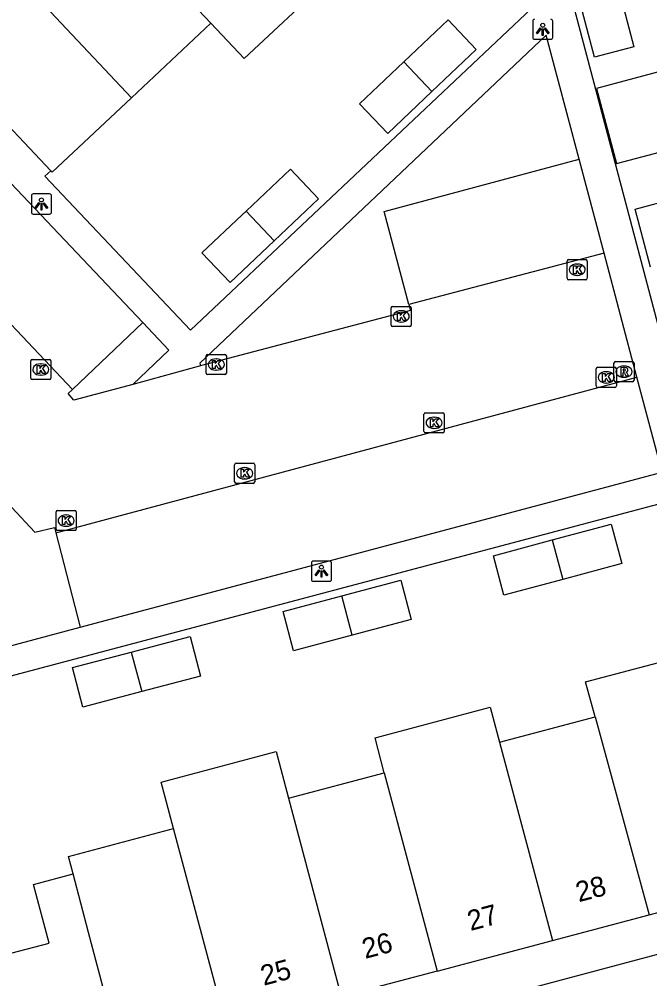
# Model space of a CAD drawing. Extents: x 162542 to 163144, y 380786 to 381511.
# Drawn here: x 162698.04 to 162729.3, y 381201.72 to 381249.34 of the extents above; entities that cross this region are included whole.
import ezdxf

# ---------------------------------------------------------------- set-up
doc = ezdxf.new("R2010")
doc.units = 0
for name, color, linetype in [('IMGEO_Kolk', 7, 'Continuous'), ('IMGEO_Lichtpunt', 7, 'Continuous'), ('IMGEO_Pand', 7, 'Continuous'), ('IMGEO_Pand_nummerreeks', 7, 'Continuous'), ('IMGEO_Parkeervlak_open', 7, 'Continuous'), ('IMGEO_Rijbaan_lokaal_open', 7, 'Continuous'), ('IMGEO_Rioolput', 7, 'Continuous'), ('IMGEO_Voetpad_open', 7, 'Continuous')]:
    doc.layers.add(name, color=color, linetype=linetype)

msp = doc.modelspace()

# ---------------------------------------------------------------- linework, layer by layer
at = {"layer": 'IMGEO_Kolk'}
for p, q in [((162725.2, 381236.483), (162725.2, 381237.335)), ((162725.275, 381237.409), (162726.127, 381237.409)), ((162725.688, 381237.189), (162725.713, 381237.189)), ((162726.201, 381237.335), (162726.201, 381236.483)), ((162725.711, 381236.629), (162725.686, 381236.629)), ((162726.127, 381236.409), (162725.275, 381236.409)), ((162716.476, 381234.166), (162716.476, 381235.018)), ((162716.551, 381235.092), (162717.403, 381235.092)), ((162716.964, 381234.872), (162716.989, 381234.872)), ((162717.477, 381235.018), (162717.477, 381234.166)), ((162716.987, 381234.312), (162716.962, 381234.312)), ((162717.403, 381234.092), (162716.551, 381234.092)), ((162698.607, 381231.533), (162698.607, 381232.385)), ((162698.682, 381232.459), (162699.534, 381232.459)), ((162699.608, 381232.385), (162699.608, 381231.533)), ((162707.307, 381231.779), (162707.307, 381232.631)), ((162707.382, 381232.705), (162708.234, 381232.705)), ((162707.795, 381232.485), (162707.82, 381232.485)), ((162708.308, 381232.631), (162708.308, 381231.779)), ((162699.095, 381232.239), (162699.12, 381232.239)), ((162707.818, 381231.925), (162707.793, 381231.925)), ((162726.643, 381231.14), (162726.643, 381231.992)), ((162726.718, 381232.066), (162727.57, 381232.066)), ((162727.131, 381231.846), (162727.156, 381231.846)), ((162727.644, 381231.992), (162727.644, 381231.14)), ((162699.534, 381231.459), (162698.682, 381231.459)), ((162699.118, 381231.679), (162699.093, 381231.679)), ((162708.234, 381231.705), (162707.382, 381231.705)), ((162727.57, 381231.066), (162726.718, 381231.066)), ((162727.154, 381231.286), (162727.129, 381231.286)), ((162718.106, 381228.888), (162718.106, 381229.74)), ((162718.181, 381229.814), (162719.033, 381229.814)), ((162718.594, 381229.594), (162718.619, 381229.594)), ((162719.107, 381229.74), (162719.107, 381228.888)), ((162718.617, 381229.034), (162718.592, 381229.034)), ((162719.033, 381228.814), (162718.181, 381228.814)), ((162708.714, 381226.382), (162708.714, 381227.234)), ((162708.789, 381227.308), (162709.641, 381227.308)), ((162709.202, 381227.088), (162709.227, 381227.088)), ((162709.715, 381227.234), (162709.715, 381226.382)), ((162709.641, 381226.308), (162708.789, 381226.308)), ((162709.225, 381226.528), (162709.2, 381226.528)), ((162699.861, 381224.036), (162699.861, 381224.888)), ((162699.936, 381224.962), (162700.788, 381224.962)), ((162700.349, 381224.742), (162700.374, 381224.742)), ((162700.862, 381224.888), (162700.862, 381224.036)), ((162700.788, 381223.962), (162699.936, 381223.962)), ((162700.372, 381224.182), (162700.347, 381224.182))]:
    msp.add_line(p, q, dxfattribs=at)
for points in [[(162725.2, 381236.483), (162725.2, 381237.335)], [(162725.275, 381237.409), (162726.127, 381237.409)], [(162725.521, 381237.109), (162725.644, 381237.109), (162725.644, 381236.958), (162725.774, 381237.109), (162725.938, 381237.109), (162725.792, 381236.958), (162725.945, 381236.709), (162725.793, 381236.709), (162725.708, 381236.873), (162725.644, 381236.806), (162725.644, 381236.709), (162725.521, 381236.709), (162725.521, 381237.109)], [(162726.201, 381237.335), (162726.201, 381236.483)], [(162726.127, 381236.409), (162725.275, 381236.409)], [(162716.476, 381234.166), (162716.476, 381235.018)], [(162716.551, 381235.092), (162717.403, 381235.092)], [(162716.797, 381234.792), (162716.92, 381234.792), (162716.92, 381234.641), (162717.05, 381234.792), (162717.214, 381234.792), (162717.068, 381234.641), (162717.221, 381234.392), (162717.069, 381234.392), (162716.984, 381234.556), (162716.92, 381234.489), (162716.92, 381234.392), (162716.797, 381234.392), (162716.797, 381234.792)], [(162717.477, 381235.018), (162717.477, 381234.166)], [(162717.403, 381234.092), (162716.551, 381234.092)], [(162698.607, 381231.533), (162698.607, 381232.385)], [(162698.682, 381232.459), (162699.534, 381232.459)], [(162699.608, 381232.385), (162699.608, 381231.533)], [(162707.307, 381231.779), (162707.307, 381232.631)], [(162707.382, 381232.705), (162708.234, 381232.705)], [(162707.628, 381232.405), (162707.751, 381232.405), (162707.751, 381232.254), (162707.881, 381232.405), (162708.045, 381232.405), (162707.899, 381232.254), (162708.052, 381232.005), (162707.9, 381232.005), (162707.815, 381232.169), (162707.751, 381232.102), (162707.751, 381232.005), (162707.628, 381232.005), (162707.628, 381232.405)], [(162708.308, 381232.631), (162708.308, 381231.779)], [(162698.928, 381232.159), (162699.051, 381232.159), (162699.051, 381232.008), (162699.181, 381232.159), (162699.345, 381232.159), (162699.199, 381232.008), (162699.352, 381231.759), (162699.2, 381231.759), (162699.115, 381231.923), (162699.051, 381231.856), (162699.051, 381231.759), (162698.928, 381231.759), (162698.928, 381232.159)], [(162726.643, 381231.14), (162726.643, 381231.992)], [(162726.718, 381232.066), (162727.57, 381232.066)], [(162727.644, 381231.992), (162727.644, 381231.14)], [(162699.534, 381231.459), (162698.682, 381231.459)], [(162708.234, 381231.705), (162707.382, 381231.705)], [(162726.964, 381231.766), (162727.087, 381231.766), (162727.087, 381231.615), (162727.217, 381231.766), (162727.381, 381231.766), (162727.235, 381231.615), (162727.388, 381231.366), (162727.236, 381231.366), (162727.151, 381231.53), (162727.087, 381231.463), (162727.087, 381231.366), (162726.964, 381231.366), (162726.964, 381231.766)], [(162727.57, 381231.066), (162726.718, 381231.066)], [(162718.106, 381228.888), (162718.106, 381229.74)], [(162718.181, 381229.814), (162719.033, 381229.814)], [(162718.427, 381229.514), (162718.55, 381229.514), (162718.55, 381229.363), (162718.68, 381229.514), (162718.844, 381229.514), (162718.698, 381229.363), (162718.851, 381229.114), (162718.699, 381229.114), (162718.614, 381229.278), (162718.55, 381229.211), (162718.55, 381229.114), (162718.427, 381229.114), (162718.427, 381229.514)], [(162719.107, 381229.74), (162719.107, 381228.888)], [(162719.033, 381228.814), (162718.181, 381228.814)], [(162708.714, 381226.382), (162708.714, 381227.234)], [(162708.789, 381227.308), (162709.641, 381227.308)], [(162709.715, 381227.234), (162709.715, 381226.382)], [(162709.035, 381227.008), (162709.158, 381227.008), (162709.158, 381226.857), (162709.288, 381227.008), (162709.452, 381227.008), (162709.306, 381226.857), (162709.459, 381226.608), (162709.307, 381226.608), (162709.222, 381226.772), (162709.158, 381226.705), (162709.158, 381226.608), (162709.035, 381226.608), (162709.035, 381227.008)], [(162709.641, 381226.308), (162708.789, 381226.308)], [(162699.861, 381224.036), (162699.861, 381224.888)], [(162699.936, 381224.962), (162700.788, 381224.962)], [(162700.862, 381224.888), (162700.862, 381224.036)], [(162700.182, 381224.662), (162700.305, 381224.662), (162700.305, 381224.511), (162700.435, 381224.662), (162700.599, 381224.662), (162700.453, 381224.511), (162700.606, 381224.262), (162700.454, 381224.262), (162700.369, 381224.426), (162700.305, 381224.359), (162700.305, 381224.262), (162700.182, 381224.262), (162700.182, 381224.662)], [(162700.788, 381223.962), (162699.936, 381223.962)]]:
    msp.add_lwpolyline(points, dxfattribs=at)
for centre, start, end in [((162725.277, 381237.333), 91.552, 178.448), ((162725.277, 381237.333), 91.552, 178.448), ((162726.125, 381237.333), 1.552, 88.448), ((162726.125, 381237.333), 1.552, 88.448), ((162725.277, 381236.485), 181.552, 268.448), ((162725.277, 381236.485), 181.552, 268.448), ((162726.125, 381236.485), 271.552, 358.448), ((162726.125, 381236.485), 271.552, 358.448), ((162716.553, 381235.016), 91.552, 178.448), ((162716.553, 381235.016), 91.552, 178.448), ((162717.401, 381235.016), 1.552, 88.448), ((162717.401, 381235.016), 1.552, 88.448), ((162716.553, 381234.168), 181.552, 268.448), ((162716.553, 381234.168), 181.552, 268.448), ((162717.401, 381234.168), 271.552, 358.448), ((162717.401, 381234.168), 271.552, 358.448), ((162698.684, 381232.383), 91.552, 178.448), ((162698.684, 381232.383), 91.552, 178.448), ((162699.532, 381232.383), 1.552, 88.448), ((162699.532, 381232.383), 1.552, 88.448), ((162707.384, 381232.629), 91.552, 178.448), ((162707.384, 381232.629), 91.552, 178.448), ((162708.232, 381232.629), 1.552, 88.448), ((162708.232, 381232.629), 1.552, 88.448), ((162726.72, 381231.99), 91.552, 178.448), ((162726.72, 381231.99), 91.552, 178.448), ((162727.568, 381231.99), 1.552, 88.448), ((162727.568, 381231.99), 1.552, 88.448), ((162698.684, 381231.535), 181.552, 268.448), ((162698.684, 381231.535), 181.552, 268.448), ((162699.532, 381231.535), 271.552, 358.448), ((162699.532, 381231.535), 271.552, 358.448), ((162707.384, 381231.781), 181.552, 268.448), ((162707.384, 381231.781), 181.552, 268.448), ((162708.232, 381231.781), 271.552, 358.448), ((162708.232, 381231.781), 271.552, 358.448), ((162726.72, 381231.142), 181.552, 268.448), ((162726.72, 381231.142), 181.552, 268.448), ((162727.568, 381231.142), 271.552, 358.448), ((162727.568, 381231.142), 271.552, 358.448), ((162718.183, 381229.738), 91.552, 178.448), ((162718.183, 381229.738), 91.552, 178.448), ((162719.031, 381229.738), 1.552, 88.448), ((162719.031, 381229.738), 1.552, 88.448), ((162718.183, 381228.89), 181.552, 268.448), ((162718.183, 381228.89), 181.552, 268.448), ((162719.031, 381228.89), 271.552, 358.448), ((162719.031, 381228.89), 271.552, 358.448), ((162708.791, 381227.232), 91.552, 178.448), ((162708.791, 381227.232), 91.552, 178.448), ((162709.639, 381227.232), 1.552, 88.448), ((162709.639, 381227.232), 1.552, 88.448), ((162708.791, 381226.384), 181.552, 268.448), ((162708.791, 381226.384), 181.552, 268.448), ((162709.639, 381226.384), 271.552, 358.448), ((162709.639, 381226.384), 271.552, 358.448), ((162699.938, 381224.886), 91.552, 178.448), ((162699.938, 381224.886), 91.552, 178.448), ((162700.786, 381224.886), 1.552, 88.448), ((162700.786, 381224.886), 1.552, 88.448), ((162699.938, 381224.038), 181.552, 268.448), ((162699.938, 381224.038), 181.552, 268.448), ((162700.786, 381224.038), 271.552, 358.448), ((162700.786, 381224.038), 271.552, 358.448)]:
    msp.add_arc(centre, 0.0765, start, end, dxfattribs=at)
for centre, major_axis, ratio, start_param, end_param in [((162725.687, 381236.909), (-0.387, 0.002), 0.722429, 4.712389, 7.853982), ((162725.712, 381236.909), (-0.39, 0.002), 0.717154, 1.570796, 4.712389), ((162716.963, 381234.592), (-0.387, 0.002), 0.722429, 4.712389, 7.853982), ((162716.988, 381234.592), (-0.39, 0.002), 0.717154, 1.570796, 4.712389), ((162707.794, 381232.205), (-0.387, 0.002), 0.722429, 4.712389, 7.853982), ((162707.819, 381232.205), (-0.39, 0.002), 0.717154, 1.570796, 4.712389), ((162699.094, 381231.959), (-0.387, 0.002), 0.722429, 4.712389, 7.853982), ((162699.119, 381231.959), (-0.39, 0.002), 0.717154, 1.570796, 4.712389), ((162727.13, 381231.566), (-0.387, 0.002), 0.722429, 4.712389, 7.853982), ((162727.155, 381231.566), (-0.39, 0.002), 0.717154, 1.570796, 4.712389), ((162718.593, 381229.314), (-0.387, 0.002), 0.722429, 4.712389, 7.853982), ((162718.618, 381229.314), (-0.39, 0.002), 0.717154, 1.570796, 4.712389), ((162709.201, 381226.808), (-0.387, 0.002), 0.722429, 4.712389, 7.853982), ((162709.226, 381226.808), (-0.39, 0.002), 0.717154, 1.570796, 4.712389), ((162700.348, 381224.462), (-0.387, 0.002), 0.722429, 4.712389, 7.853982), ((162700.373, 381224.462), (-0.39, 0.002), 0.717154, 1.570796, 4.712389)]:
    msp.add_ellipse(centre, major_axis=major_axis, ratio=ratio, start_param=start_param, end_param=end_param, dxfattribs=at)
at = {"layer": 'IMGEO_Lichtpunt'}
for p, q in [((162723.495, 381249.246), (162723.495, 381248.439)), ((162723.495, 381249.246), (162723.495, 381248.439)), ((162724.491, 381248.439), (162724.491, 381249.246)), ((162724.491, 381248.439), (162724.491, 381249.246)), ((162723.589, 381248.345), (162724.397, 381248.345)), ((162723.589, 381248.345), (162724.397, 381248.345)), ((162698.641, 381240.573), (162698.641, 381239.766)), ((162698.641, 381240.573), (162698.641, 381239.766)), ((162699.543, 381240.668), (162698.735, 381240.668)), ((162699.543, 381240.668), (162698.735, 381240.668)), ((162699.637, 381239.766), (162699.637, 381240.573)), ((162699.637, 381239.766), (162699.637, 381240.573)), ((162698.735, 381239.672), (162699.543, 381239.672)), ((162698.735, 381239.672), (162699.543, 381239.672)), ((162712.524, 381222.354), (162712.524, 381221.547)), ((162712.524, 381222.354), (162712.524, 381221.547)), ((162713.426, 381222.449), (162712.618, 381222.449)), ((162713.426, 381222.449), (162712.618, 381222.449)), ((162713.52, 381221.547), (162713.52, 381222.354)), ((162713.52, 381221.547), (162713.52, 381222.354)), ((162712.618, 381221.453), (162713.426, 381221.453)), ((162712.618, 381221.453), (162713.426, 381221.453))]:
    msp.add_line(p, q, dxfattribs=at)
for points in [[(162723.869, 381248.91), (162723.908, 381248.882), (162723.72, 381248.62), (162723.682, 381248.647), (162723.869, 381248.91)], [(162723.971, 381248.862), (162724.018, 381248.862), (162724.018, 381248.54), (162723.971, 381248.54), (162723.971, 381248.862)], [(162724.081, 381248.882), (162724.119, 381248.909), (162724.306, 381248.647), (162724.267, 381248.619), (162724.081, 381248.882)], [(162699.015, 381240.237), (162699.054, 381240.209), (162698.866, 381239.947), (162698.828, 381239.974), (162699.015, 381240.237)], [(162699.117, 381240.189), (162699.164, 381240.189), (162699.164, 381239.867), (162699.117, 381239.867), (162699.117, 381240.189)], [(162699.227, 381240.209), (162699.265, 381240.236), (162699.452, 381239.974), (162699.413, 381239.946), (162699.227, 381240.209)], [(162712.898, 381222.018), (162712.937, 381221.99), (162712.749, 381221.728), (162712.711, 381221.755), (162712.898, 381222.018)], [(162713, 381221.97), (162713.047, 381221.97), (162713.047, 381221.648), (162713, 381221.648), (162713, 381221.97)], [(162713.11, 381221.99), (162713.148, 381222.017), (162713.335, 381221.755), (162713.296, 381221.727), (162713.11, 381221.99)]]:
    msp.add_lwpolyline(points, dxfattribs=at)
for centre in [(162723.994, 381249.044), (162699.14, 381240.371), (162713.023, 381222.152)]:
    msp.add_circle(centre, 0.0994, dxfattribs=at)
for centre, start, end in [((162723.589, 381249.246), 90, 180), ((162723.589, 381249.246), 90, 180), ((162724.397, 381249.246), 0, 90), ((162724.397, 381249.246), 0, 90), ((162723.589, 381248.439), 180, 270), ((162723.589, 381248.439), 180, 270), ((162724.397, 381248.439), 270, 0), ((162724.397, 381248.439), 270, 360), ((162698.735, 381240.573), 90, 180), ((162698.735, 381240.573), 90, 180), ((162699.543, 381240.573), 0, 90), ((162699.543, 381240.573), 0, 90), ((162698.735, 381239.766), 180, 270), ((162698.735, 381239.766), 180, 270), ((162699.543, 381239.766), 270, 0), ((162699.543, 381239.766), 270, 360), ((162712.618, 381222.354), 90, 180), ((162712.618, 381222.354), 90, 180), ((162713.426, 381222.354), 0, 90), ((162713.426, 381222.354), 0, 90), ((162712.618, 381221.547), 180, 270), ((162712.618, 381221.547), 180, 270), ((162713.426, 381221.547), 270, 0), ((162713.426, 381221.547), 270, 360)]:
    msp.add_arc(centre, 0.0946, start, end, dxfattribs=at)
at = {"layer": 'IMGEO_Pand'}
for points in [[(162707.53, 381249.144), (162700.536, 381256.552)], [(162696.614, 381252.86), (162703.604, 381245.444)], [(162707.53, 381249.144), (162709.189, 381247.387), (162713.298, 381251.249)], [(162728.518, 381247.977), (162726.564, 381247.458), (162725.794, 381250.355), (162727.745, 381250.883), (162728.518, 381247.977)], [(162692.684, 381249.159), (162699.606, 381241.818)], [(162703.604, 381245.444), (162707.53, 381249.144)], [(162718.499, 381245.754), (162720.69, 381247.831), (162719.3, 381249.303), (162717.106, 381247.224)], [(162717.106, 381247.224), (162714.915, 381245.147), (162716.308, 381243.677), (162718.499, 381245.754)], [(162718.499, 381245.754), (162717.106, 381247.224)], [(162730.367, 381246.893), (162726.662, 381245.909), (162727.653, 381242.178), (162731.357, 381243.162), (162730.367, 381246.893)], [(162699.606, 381241.818), (162699.677, 381241.743), (162703.604, 381245.444)], [(162710.683, 381238.348), (162712.876, 381240.422), (162711.482, 381241.895), (162709.289, 381239.822)], [(162729.334, 381237.037), (162728.568, 381239.917), (162730.536, 381240.438), (162731.294, 381237.569)], [(162709.289, 381239.822), (162709.084, 381239.628), (162707.088, 381237.741), (162708.49, 381236.274), (162710.683, 381238.348)], [(162710.683, 381238.348), (162709.289, 381239.822)], [(162724.468, 381223.499), (162727.387, 381224.28), (162727.911, 381222.324), (162724.992, 381221.543)], [(162724.992, 381221.543), (162722.072, 381220.761), (162721.556, 381222.72), (162724.468, 381223.499)], [(162724.468, 381223.499), (162724.992, 381221.543)], [(162714.034, 381220.723), (162716.95, 381221.503), (162717.469, 381219.561), (162714.552, 381218.783)], [(162714.552, 381218.783), (162711.635, 381218.004), (162711.121, 381219.944), (162714.034, 381220.723)], [(162714.552, 381218.783), (162714.034, 381220.723)], [(162703.595, 381217.937), (162706.51, 381218.705), (162707.032, 381216.744), (162704.112, 381215.976)], [(162704.112, 381215.976), (162701.191, 381215.207), (162700.675, 381217.167), (162703.595, 381217.937)], [(162703.595, 381217.937), (162704.112, 381215.976)], [(162726.586, 381214.725), (162726.113, 381216.459), (162731.811, 381217.971), (162731.839, 381217.865)], [(162716.137, 381211.949), (162715.678, 381213.677), (162721.392, 381215.196), (162721.852, 381213.468)], [(162721.852, 381213.468), (162726.586, 381214.725)], [(162726.586, 381214.725), (162729.268, 381204.894)], [(162721.852, 381213.468), (162724.473, 381203.621)], [(162705.693, 381209.175), (162705.078, 381211.488), (162710.779, 381213.004), (162711.391, 381210.689)], [(162711.391, 381210.689), (162716.137, 381211.949)], [(162716.137, 381211.949), (162718.757, 381202.103)], [(162711.391, 381210.689), (162713.994, 381200.841)], [(162700.704, 381206.928), (162700.475, 381207.789), (162705.693, 381209.175)], [(162708.31, 381199.334), (162705.693, 381209.175)], [(162693.566, 381201.906), (162693.946, 381202.007), (162697.691, 381203.007), (162699.525, 381203.496), (162698.751, 381206.41), (162700.704, 381206.928)], [(162703.116, 381197.844), (162701.477, 381204.017), (162700.704, 381206.928)], [(162729.268, 381204.894), (162734.886, 381206.386)], [(162724.473, 381203.621), (162729.268, 381204.894)], [(162718.757, 381202.103), (162724.473, 381203.621)], [(162718.757, 381202.103), (162713.994, 381200.841)]]:
    msp.add_lwpolyline(points, dxfattribs=at)
at = {"layer": 'IMGEO_Parkeervlak_open'}
for points in [[(162717.359, 381235.188), (162716.135, 381239.802), (162725.799, 381242.395)], [(162700.677, 381230.974), (162704.173, 381234.294)], [(162699.849, 381223.847), (162701.06, 381219.172)]]:
    msp.add_lwpolyline(points, dxfattribs=at)
at = {"layer": 'IMGEO_Rijbaan_lokaal_open'}
for points in [[(162700.677, 381230.974), (162688.475, 381243.889), (162691.953, 381247.17)], [(162727.036, 381237.729), (162717.359, 381235.188)], [(162728.656, 381231.579), (162727.036, 381237.729)], [(162717.359, 381235.188), (162717.44, 381234.879), (162707.144, 381232.175), (162707.019, 381232.142)], [(162707.019, 381232.142), (162703.666, 381231.209)], [(162699.849, 381223.847), (162728.656, 381231.579)], [(162703.666, 381231.209), (162700.747, 381230.44), (162700.456, 381230.763), (162700.677, 381230.974)], [(162697.438, 381224.879), (162697.666, 381225.113), (162698.805, 381223.893), (162699.779, 381224.12), (162699.849, 381223.847)]]:
    msp.add_lwpolyline(points, dxfattribs=at)
at = {"layer": 'IMGEO_Rioolput'}
for p, q in [((162727.597, 381232.35), (162728.449, 381232.35)), ((162727.522, 381231.424), (162727.522, 381232.276)), ((162728.01, 381232.13), (162728.035, 381232.13)), ((162728.523, 381232.276), (162728.523, 381231.424)), ((162728.033, 381231.57), (162728.008, 381231.57)), ((162728.449, 381231.35), (162727.597, 381231.35))]:
    msp.add_line(p, q, dxfattribs=at)
for points in [[(162727.597, 381232.35), (162728.449, 381232.35)], [(162727.522, 381231.424), (162727.522, 381232.276)], [(162728.111, 381232.048), (162727.859, 381232.05), (162727.859, 381231.65)], [(162728.037, 381231.969), (162727.983, 381231.969), (162727.983, 381231.888)], [(162727.983, 381231.888), (162728.035, 381231.888)], [(162728.523, 381232.276), (162728.523, 381231.424)], [(162727.859, 381231.65), (162727.983, 381231.65), (162727.983, 381231.812), (162727.994, 381231.812)], [(162728.041, 381231.783), (162728.112, 381231.65), (162728.252, 381231.65), (162728.187, 381231.776)], [(162728.449, 381231.35), (162727.597, 381231.35)]]:
    msp.add_lwpolyline(points, dxfattribs=at)
for centre, radius, start, end in [((162727.599, 381232.274), 0.0765, 91.552, 178.448), ((162727.599, 381232.274), 0.0765, 91.552, 178.448), ((162728.447, 381232.274), 0.0765, 1.552, 88.448), ((162728.447, 381232.274), 0.0765, 1.552, 88.448), ((162728.019, 381232.077), 0.19, 274.7715, 282.9687), ((162728.043, 381231.873), 0.0964, 77.0061, 93.1865), ((162728.057, 381231.93), 0.0378, 276.6634, 79.6772), ((162728.11, 381231.938), 0.109, 350.3612, 89.416), ((162728.108, 381231.938), 0.112, 277.5842, 350.9817), ((162727.599, 381231.426), 0.0765, 181.552, 268.448), ((162727.599, 381231.426), 0.0765, 181.552, 268.448), ((162727.993, 381231.759), 0.0533, 26.0293, 88.6989), ((162728.092, 381231.723), 0.108, 29.5134, 73.7905), ((162728.447, 381231.426), 0.0765, 271.552, 358.448), ((162728.447, 381231.426), 0.0765, 271.552, 358.448)]:
    msp.add_arc(centre, radius, start, end, dxfattribs=at)
for centre, major_axis, ratio, start_param, end_param in [((162728.009, 381231.85), (-0.387, 0.002), 0.722429, 4.712389, 7.853982), ((162728.034, 381231.85), (-0.39, 0.002), 0.717154, 1.570796, 4.712389)]:
    msp.add_ellipse(centre, major_axis=major_axis, ratio=ratio, start_param=start_param, end_param=end_param, dxfattribs=at)
at = {"layer": 'IMGEO_Voetpad_open'}
for points in [[(162719.215, 381274.137), (162721.568, 381264.953), (162735.925, 381210.607)], [(162720.077, 381263.689), (162720.445, 381263.784), (162722.828, 381254.89), (162723.533, 381252.257), (162723.915, 381250.834), (162724.022, 381250.433), (162708.241, 381235.532), (162706.532, 381233.918), (162699.315, 381241.544), (162699.606, 381241.818)], [(162725.799, 381242.395), (162724.166, 381248.556), (162706.988, 381232.279), (162707.019, 381232.142)], [(162704.173, 381234.294), (162691.953, 381247.17)], [(162727.036, 381237.729), (162725.799, 381242.395)], [(162703.666, 381231.209), (162705.462, 381232.918), (162704.173, 381234.294)], [(162731.839, 381217.865), (162732.225, 381217.967), (162730.249, 381225.411), (162696.73, 381216.515), (162682.628, 381231.503), (162682.331, 381231.223)], [(162701.06, 381219.172), (162729.91, 381226.858), (162728.656, 381231.579)], [(162693.896, 381221.629), (162697.175, 381218.132), (162701.06, 381219.172)], [(162690.949, 381192.615), (162735.396, 381204.465)]]:
    msp.add_lwpolyline(points, dxfattribs=at)

# ---------------------------------------------------------------- texts
at = {"layer": 'IMGEO_Pand_nummerreeks'}
for s, rotation, p in [('28', 14.8683, (162725.78, 381205.52)), ('27', 14.874, (162720.412, 381204.095)), ('26', 14.8396, (162715.19, 381202.709)), ('25', 14.8511, (162710.157, 381201.375))]:
    msp.add_text(s, height=1, rotation=rotation, dxfattribs=at).set_placement(p)

doc.saveas('drawing.dxf')
